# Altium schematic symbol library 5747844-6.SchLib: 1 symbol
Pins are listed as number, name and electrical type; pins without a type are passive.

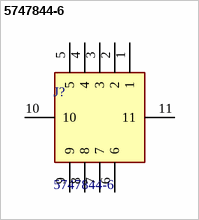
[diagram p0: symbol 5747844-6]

## 5747844-6
designator J?
Body Features: Connector Profile Standard | Mating Feature Material Zinc | Assembly Process Feature Material Copper Alloy | Mating Feature Plating Material Clear Chromate | Primary Product Color Black | Shell Plating Material Tin | Insert Material Zinc | Configuration Features: Number of Rows 2 | Number of Positions 9 | PCB Mount Orientation Right Angle | Contact Features: Contact Base Material Phosphor Bronze | Contact Mating Area Plating Material Thickness 30 MICIN | Contact Mating Area Plating Material G; Manufacturer_Name: TE Connectivity; Geometry.Height: 12mm
footprint 57478446
pins: 1, 2, 3, 4, 5, 6, 7, 8, 9, 10, 11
